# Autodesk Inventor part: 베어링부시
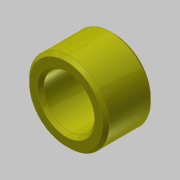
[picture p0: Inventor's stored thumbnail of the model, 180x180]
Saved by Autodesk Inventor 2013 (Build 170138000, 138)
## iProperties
Created: 2019-03
Part Number: 베어링부시
Material: 강철, 연강
Document SubType Name: Modeling
Designer: mduedu
Density: 1 g/cm^3
Author: mduedu
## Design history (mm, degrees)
sketch "스케치1"
  geometry: L1 (-7.5, 12.5)-(7.5, 12.5); L2 (7.5, 12.5)-(7.5, 8); L3 (7.5, 8)-(-7.5, 8); L4 (-7.5, 8)-(-7.5, 12.5); L5 (-7.5, 0)-(7.5, 0); 3 further points
  constraints: 10 end point, 2 midpoint, 2 parallel, 2 perpendicular, 2 vertical alignment, 1 coincident, 1 horizontal
  dimensions: "d0" = 16 diameter of L3 L5; "d2" = 25 diameter of L1 L5; "d3" = 15 distance of L1.start L1.end
revolve "회전1" sketch "스케치1" stored, may be unused: angle "d4" = 90 deg
chamfer "모따기1" distance "d5" = 1; stored, may be unused: second distance "d6" = 2, angle "d7" = 45 deg
chamfer "모따기2" distance "d8" = 1; stored, may be unused: second distance "d9" = 2, angle "d10" = 45 deg
node "솔리드1"
